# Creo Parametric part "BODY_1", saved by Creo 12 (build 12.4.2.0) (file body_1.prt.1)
Units: Custom; MM, KILOGRAM, SECS

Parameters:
  PTC_WM_ITERATION = "0"
  PTC_WM_VERSION = "-.0"
  PTC_WM_LIFECYCLE_STATE = "In Work"
  PTC_WM_LIFECYCLE = "MO_CADDocument"
  PTC_WM_CREATED_BY = "Maximilian Roepper (Z0017RMS: MO)"
  PTC_WM_CREATED_ON = "18-Sep-26 11:36:42 AM"
  PTC_WM_MODIFIED_BY = "Maximilian Roepper (Z0017RMS: MO)"
  PTC_WM_MODIFIED_ON = "18-Sep-26 11:36:46 AM"
  PDMLINKNUMBER = "PDM000071455290"
  PTC_WM_NAME = "body_1.prt"
  PTC_WM_NUMBER = "PDM000071455290"

Other parameters: WEIGHT, WEIGHT_FACTOR, WEIGHT_ADD, _MASS_TEMP, _DIFF_TEMP, MC_ERRORS, SUPPLIER

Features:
  1. coordinate system
  2. datum plane "PRT_YZ"
  3. datum plane "PRT_XY"
  4. datum plane "PRT_XZ"
  5. coordinate system
  6. datum axis
  7. datum axis
  8. datum axis
  9. coordinate system
  10. imported feature

Other named items: PRT, SIEMENS_MO, DRW_VIEW_ORG, PRT_X, PRT_Y, PRT_Z, CS0, ROUGH_GROB

Layers: 00_STD_CSYS-KSYS, 01_STD_PLANES-EBENEN, 02_STD_AXES-ACHSEN, 03_STD_CSYS-KSYS, 24_IMPORT_FEAT-IMPORT_KE

Surfaces: 6 plane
